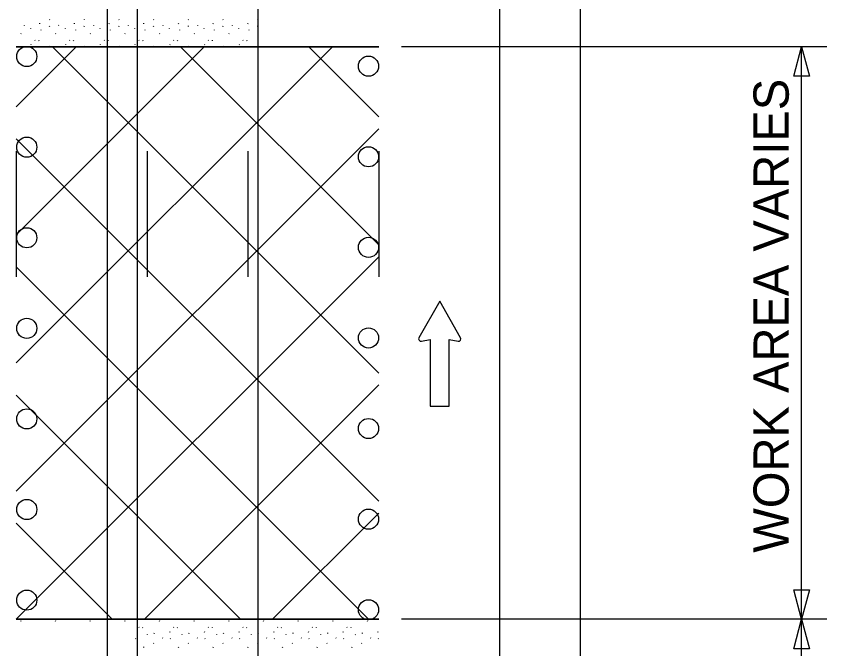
# Model space of a CAD drawing. Extents: x 16735 to 18475, y 6983 to 8262.
# Drawn here: x 17017.1 to 17178.1, y 7738.8 to 7864.5 of the extents above; entities that cross this region are included whole.
import ezdxf

# ---------------------------------------------------------------- set-up
doc = ezdxf.new("R2010")
doc.units = 0
for name, color, linetype in [('ALI_LEGAL_EX', 7, 'Continuous'), ('MT_SCRATCH_LEVEL_A', 7, 'Continuous'), ('MT_SCRATCH_LEVEL_E', 7, 'Continuous'), ('PAVT_EDGE_EX', 7, 'Continuous'), ('TRAFFIC_SIGNS_PR', 7, 'Continuous'), ('TYPICAL_TEXT_DIMEN_PR', 7, 'Continuous')]:
    doc.layers.add(name, color=color, linetype=linetype)

msp = doc.modelspace()

# ---------------------------------------------------------------- linework, layer by layer
at = {"layer": 'ALI_LEGAL_EX'}
for points in [[(17017.08, 7837.7), (17017.08, 7812.7)], [(17043.08, 7837.7), (17043.08, 7812.7)], [(17063.08, 7837.7), (17063.08, 7812.7)], [(17089.08, 7837.7), (17089.08, 7812.7)]]:
    msp.add_lwpolyline(points, dxfattribs=at)
at = {"layer": 'MT_SCRATCH_LEVEL_A'}
for p, q in [((17023.67, 7863.89), (17023.73, 7863.82)), ((17030.56, 7863.89), (17030.61, 7863.82)), ((17037.45, 7863.89), (17037.5, 7863.82)), ((17044.34, 7863.89), (17044.39, 7863.82)), ((17051.22, 7863.89), (17051.28, 7863.82)), ((17058.11, 7863.89), (17058.16, 7863.82)), ((17065, 7863.89), (17065.05, 7863.82)), ((17018.63, 7862.74), (17018.68, 7862.67)), ((17019.91, 7862.17), (17019.92, 7862.05)), ((17021.75, 7863.02), (17021.8, 7863.14)), ((17021.94, 7861.83), (17021.99, 7861.75)), ((17023.72, 7862.49), (17023.77, 7862.61)), ((17025.51, 7862.74), (17025.57, 7862.67)), ((17026.8, 7862.17), (17026.81, 7862.05)), ((17028.64, 7863.02), (17028.69, 7863.14)), ((17028.83, 7861.83), (17028.88, 7861.75)), ((17030.6, 7862.49), (17030.66, 7862.61)), ((17032.4, 7862.74), (17032.45, 7862.67)), ((17033.68, 7862.17), (17033.7, 7862.05)), ((17035.53, 7863.02), (17035.58, 7863.14)), ((17035.71, 7861.83), (17035.76, 7861.75)), ((17037.49, 7862.49), (17037.54, 7862.61)), ((17039.29, 7862.74), (17039.34, 7862.67)), ((17040.57, 7862.17), (17040.58, 7862.05)), ((17042.41, 7863.02), (17042.46, 7863.14)), ((17042.6, 7861.83), (17042.65, 7861.75)), ((17044.38, 7862.49), (17044.43, 7862.61)), ((17046.18, 7862.74), (17046.23, 7862.67)), ((17047.46, 7862.17), (17047.47, 7862.05)), ((17049.3, 7863.02), (17049.35, 7863.14)), ((17049.49, 7861.83), (17049.54, 7861.75)), ((17051.27, 7862.49), (17051.32, 7862.61)), ((17053.06, 7862.74), (17053.12, 7862.67)), ((17054.35, 7862.17), (17054.36, 7862.05)), ((17056.19, 7863.02), (17056.24, 7863.14)), ((17056.38, 7861.83), (17056.43, 7861.75)), ((17058.15, 7862.49), (17058.21, 7862.61)), ((17059.95, 7862.74), (17060, 7862.67)), ((17061.23, 7862.17), (17061.25, 7862.05)), ((17063.08, 7863.02), (17063.13, 7863.14)), ((17063.26, 7861.83), (17063.31, 7861.75)), ((17065.04, 7862.49), (17065.1, 7862.61)), ((17018.01, 7860.99), (17018.06, 7861.11)), ((17024.9, 7860.99), (17024.95, 7861.11)), ((17031.78, 7860.99), (17031.83, 7861.11)), ((17038.67, 7860.99), (17038.72, 7861.11)), ((17045.56, 7860.99), (17045.61, 7861.11)), ((17052.45, 7860.99), (17052.5, 7861.11)), ((17059.33, 7860.99), (17059.39, 7861.11)), ((17017.08, 7858.43), (17089.08, 7858.43)), ((17089.08, 7858.43), (17017.08, 7858.43)), ((17017.08, 7858.43), (17089.08, 7858.43)), ((17017.08, 7846.53), (17028.98, 7858.43)), ((17017.08, 7821.07), (17054.44, 7858.43)), ((17017.08, 7795.62), (17079.89, 7858.43)), ((17020.03, 7858.8), (17020.08, 7858.91)), ((17020.79, 7859.76), (17020.84, 7859.68)), ((17021.53, 7859.73), (17021.58, 7859.65)), ((17023.85, 7858.5), (17023.9, 7858.61)), ((17089.08, 7793.62), (17024.27, 7858.43)), ((17026.92, 7858.8), (17026.97, 7858.91)), ((17027.68, 7859.76), (17027.73, 7859.68)), ((17028.42, 7859.73), (17028.47, 7859.65)), ((17030.74, 7858.5), (17030.79, 7858.61)), ((17033.8, 7858.8), (17033.85, 7858.91)), ((17034.57, 7859.76), (17034.62, 7859.68)), ((17035.3, 7859.73), (17035.36, 7859.65)), ((17037.62, 7858.5), (17037.67, 7858.61)), ((17040.69, 7858.8), (17040.74, 7858.91)), ((17041.46, 7859.76), (17041.51, 7859.68)), ((17042.19, 7859.73), (17042.24, 7859.65)), ((17044.51, 7858.5), (17044.56, 7858.61)), ((17047.58, 7858.8), (17047.63, 7858.91)), ((17048.34, 7859.76), (17048.39, 7859.68)), ((17049.08, 7859.73), (17049.13, 7859.65)), ((17089.08, 7819.08), (17049.73, 7858.43)), ((17051.4, 7858.5), (17051.45, 7858.61)), ((17054.47, 7858.8), (17054.52, 7858.91)), ((17055.23, 7859.76), (17055.28, 7859.68)), ((17055.97, 7859.73), (17056.02, 7859.65)), ((17058.28, 7858.5), (17058.34, 7858.61)), ((17061.35, 7858.8), (17061.4, 7858.91)), ((17062.12, 7859.76), (17062.17, 7859.68)), ((17062.85, 7859.73), (17062.91, 7859.65)), ((17089.08, 7844.53), (17075.18, 7858.43)), ((17017.08, 7770.16), (17089.08, 7842.16)), ((17089.08, 7768.16), (17017.08, 7840.16)), ((17017.08, 7744.71), (17089.08, 7816.71)), ((17087.08, 7744.71), (17017.08, 7814.71)), ((17042.54, 7744.71), (17089.08, 7791.25)), ((17061.63, 7744.71), (17017.08, 7789.25)), ((17067.99, 7744.71), (17089.08, 7765.79)), ((17036.17, 7744.71), (17017.08, 7763.8)), ((17017.08, 7744.71), (17089.08, 7744.71)), ((17017.08, 7744.71), (17089.08, 7744.71)), ((17089.08, 7744.71), (17017.08, 7744.71)), ((17017.08, 7744.71), (17017.08, 7744.71)), ((17018.01, 7744.35), (17018.06, 7744.46)), ((17024.9, 7744.35), (17024.95, 7744.46)), ((17031.78, 7744.35), (17031.83, 7744.46)), ((17038.67, 7744.35), (17038.72, 7744.46)), ((17045.56, 7744.35), (17045.61, 7744.46)), ((17052.45, 7744.35), (17052.5, 7744.46)), ((17059.33, 7744.35), (17059.39, 7744.46)), ((17066.22, 7744.35), (17066.27, 7744.46)), ((17073.11, 7744.35), (17073.16, 7744.46)), ((17080, 7744.35), (17080.05, 7744.46)), ((17086.88, 7744.35), (17086.94, 7744.46)), ((17041.46, 7743.11), (17041.51, 7743.03)), ((17042.19, 7743.08), (17042.24, 7743)), ((17048.34, 7743.11), (17048.39, 7743.03)), ((17049.08, 7743.08), (17049.13, 7743)), ((17055.23, 7743.11), (17055.28, 7743.03)), ((17055.97, 7743.08), (17056.02, 7743)), ((17062.12, 7743.11), (17062.17, 7743.03)), ((17062.85, 7743.08), (17062.91, 7743)), ((17069.01, 7743.11), (17069.06, 7743.03)), ((17069.74, 7743.08), (17069.79, 7743)), ((17075.89, 7743.11), (17075.94, 7743.03)), ((17076.63, 7743.08), (17076.68, 7743)), ((17082.78, 7743.11), (17082.83, 7743.03)), ((17083.52, 7743.08), (17083.57, 7743)), ((17040.77, 7740.88), (17040.82, 7740.81)), ((17043.06, 7741.7), (17043.11, 7741.62)), ((17044.51, 7741.85), (17044.56, 7741.97)), ((17046.13, 7741.02), (17046.18, 7740.95)), ((17047.58, 7742.15), (17047.63, 7742.27)), ((17047.66, 7740.88), (17047.71, 7740.81)), ((17049.95, 7741.7), (17050, 7741.62)), ((17051.4, 7741.85), (17051.45, 7741.97)), ((17053.02, 7741.02), (17053.07, 7740.95)), ((17054.47, 7742.15), (17054.52, 7742.27)), ((17054.55, 7740.88), (17054.6, 7740.81)), ((17056.84, 7741.7), (17056.89, 7741.62)), ((17058.28, 7741.85), (17058.34, 7741.97)), ((17059.9, 7741.02), (17059.96, 7740.95)), ((17061.35, 7742.15), (17061.4, 7742.27)), ((17061.43, 7740.88), (17061.49, 7740.81)), ((17063.72, 7741.7), (17063.78, 7741.62)), ((17065.17, 7741.85), (17065.22, 7741.97)), ((17066.79, 7741.02), (17066.84, 7740.95)), ((17068.24, 7742.15), (17068.29, 7742.27)), ((17068.32, 7740.88), (17068.37, 7740.81)), ((17070.61, 7741.7), (17070.66, 7741.62)), ((17072.06, 7741.85), (17072.11, 7741.97)), ((17073.68, 7741.02), (17073.73, 7740.95)), ((17075.13, 7742.15), (17075.18, 7742.27)), ((17075.21, 7740.88), (17075.26, 7740.81)), ((17077.5, 7741.7), (17077.55, 7741.62)), ((17078.95, 7741.85), (17079, 7741.97)), ((17080.57, 7741.02), (17080.62, 7740.95)), ((17082.02, 7742.15), (17082.07, 7742.27)), ((17082.1, 7740.88), (17082.15, 7740.81)), ((17084.39, 7741.7), (17084.44, 7741.62)), ((17085.83, 7741.85), (17085.89, 7741.97)), ((17087.45, 7741.02), (17087.51, 7740.95)), ((17088.9, 7742.15), (17088.96, 7742.27)), ((17088.98, 7740.88), (17089.03, 7740.81)), ((17044.34, 7739.96), (17044.39, 7739.89)), ((17051.22, 7739.96), (17051.28, 7739.89)), ((17058.11, 7739.96), (17058.16, 7739.89)), ((17065, 7739.96), (17065.05, 7739.89)), ((17071.89, 7739.96), (17071.94, 7739.89)), ((17078.78, 7739.96), (17078.83, 7739.89)), ((17085.66, 7739.96), (17085.72, 7739.89)), ((17042.41, 7739.1), (17042.46, 7739.21)), ((17049.3, 7739.1), (17049.35, 7739.21)), ((17056.19, 7739.1), (17056.24, 7739.21)), ((17063.08, 7739.1), (17063.13, 7739.21)), ((17069.96, 7739.1), (17070.01, 7739.21)), ((17076.85, 7739.1), (17076.9, 7739.21)), ((17083.74, 7739.1), (17083.79, 7739.21))]:
    msp.add_line(p, q, dxfattribs=at)
at = {"layer": 'MT_SCRATCH_LEVEL_E'}
for p, q in [((17101.19, 7807.88), (17097.08, 7800.64)), ((17101.19, 7807.88), (17097.08, 7800.64)), ((17105.33, 7800.64), (17101.19, 7807.88)), ((17105.33, 7800.64), (17101.19, 7807.88)), ((17097.56, 7799.95), (17099.33, 7800.27)), ((17097.56, 7799.95), (17099.33, 7800.27)), ((17099.33, 7800.27), (17099.33, 7787.01)), ((17099.33, 7800.27), (17099.33, 7787.01)), ((17103.08, 7787.01), (17103.08, 7800.27)), ((17103.08, 7800.27), (17104.85, 7799.95)), ((17103.08, 7787.01), (17103.08, 7800.27)), ((17103.08, 7800.27), (17104.85, 7799.95)), ((17099.33, 7787.01), (17103.08, 7787.01)), ((17099.33, 7787.01), (17103.08, 7787.01))]:
    msp.add_line(p, q, dxfattribs=at)
for centre, start, end in [((17097.48, 7800.41), 150.4248, 279.9638), ((17097.48, 7800.41), 150.4248, 279.9638), ((17104.92, 7800.41), 260.0362, 29.7731), ((17104.92, 7800.41), 260.0362, 29.7731)]:
    msp.add_arc(centre, 0.463, start, end, dxfattribs=at)
at = {"layer": 'PAVT_EDGE_EX'}
for p, q in [((17035.15, 8262.34), (17035.15, 7433.15)), ((17041.08, 8195.21), (17041.08, 7357.91)), ((17065.08, 8195.21), (17065.08, 7357.91)), ((17113.08, 8195.21), (17113.08, 7357.91)), ((17129.08, 8195.21), (17129.08, 7357.91))]:
    msp.add_line(p, q, dxfattribs=at)
at = {"layer": 'TRAFFIC_SIGNS_PR'}
for centre in [(17019.18, 7856.5), (17087.06, 7854.59), (17019.18, 7838.5), (17087.06, 7836.59), (17019.18, 7820.5), (17087.06, 7818.59), (17019.18, 7802.5), (17087.06, 7800.59), (17019.18, 7784.5), (17087.06, 7782.59), (17019.18, 7766.5), (17087.06, 7764.59), (17019.18, 7748.5), (17087.06, 7746.59)]:
    msp.add_circle(centre, 2, dxfattribs=at)
at = {"layer": 'TYPICAL_TEXT_DIMEN_PR'}
for p, q in [((17178.08, 7858.43), (17093.58, 7858.43)), ((17171.51, 7852.57), (17173.08, 7858.43)), ((17173.08, 7744.71), (17173.08, 7858.43)), ((17173.08, 7858.43), (17174.65, 7852.57)), ((17173.08, 7852.57), (17171.51, 7852.57)), ((17174.65, 7852.57), (17173.08, 7852.57)), ((17173.08, 7744.71), (17171.51, 7750.57)), ((17171.51, 7750.57), (17173.08, 7750.57)), ((17173.08, 7750.57), (17174.65, 7750.57)), ((17174.65, 7750.57), (17173.08, 7744.71)), ((17178.08, 7744.71), (17093.58, 7744.71)), ((17171.51, 7738.84), (17173.08, 7744.71)), ((17173.08, 7712.65), (17173.08, 7744.71)), ((17173.08, 7744.71), (17174.65, 7738.84)), ((17173.08, 7738.84), (17171.51, 7738.84)), ((17174.65, 7738.84), (17173.08, 7738.84))]:
    msp.add_line(p, q, dxfattribs=at)

# ---------------------------------------------------------------- texts
msp.add_text('WORK AREA VARIES', height=7, rotation=90, dxfattribs=at).set_placement((17170.52, 7757.93))

doc.saveas('drawing.dxf')
